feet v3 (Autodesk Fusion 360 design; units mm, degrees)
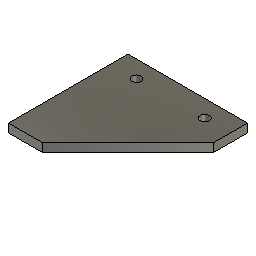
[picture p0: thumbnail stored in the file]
sketch "Sketch1" plane through (0, 0, 0) normal (0, 0, 1) x axis (1, 0, 0)
  line L1 (35, 10) -> (-35, 10)
  line L2 (35, -10) -> (35, 10)
  line L3 (-15, -60) -> (35, -10)
  line L4 (-35, -60) -> (-15, -60)
  line L5 (-35, 10) -> (-35, -60)
  point P7 (35, 0)
  point P8 (0, 10)
  point P1 (0, 0)
  point P3 (35, -10)
  point P4 (-15, -60)
  point P2 (35, 10)
  point P5 (-35, -60)
  horizontal L1
  perpendicular L1 L2
  perpendicular L2 L4
  perpendicular L4 L5
  midpoint L2 P7
  midpoint L1 P8
  vertical P1 P8
  horizontal P1 P7
  dimension "d2" distance P3 P4 = 50
  dimension "d3" distance P2 P3 = 20
  dimension "d4" angle L3 L4 = 45
  dimension "d5" distance P4 P5 = 20
extrude "Extrude1" new body sketch "Sketch1" along normal blind 5
sketch "Sketch2" plane through (0, 0, 5) normal (0, 0, 1) x axis (-1, 0, 0)
  line L1 (15, 60) -> (35, 60)
  line L2 (-35, 10) -> (15, 60)
  line L3 (-35, -10) -> (-35, 10)
  line L4 (35, -10) -> (-35, -10)
  line L5 (35, 60) -> (35, -10)
  circle C1 centre (-20, 0) radius 2.7
  circle C2 centre (20, 0) radius 2.7
  point P1 (0, 0)
  point P8 (20, 0)
  point P7 (-20, 0)
  horizontal P1 P8
  horizontal P1 P7
  dimension "d8" diameter C1 = 5.4
  dimension "d9" diameter C2 = 5.4
  dimension "d10" distance P1 P8 = 20
  dimension "d11" distance P1 P7 = 20
extrude "Extrude2" cut sketch "Sketch2" profile of C1 C2 against normal blind 10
